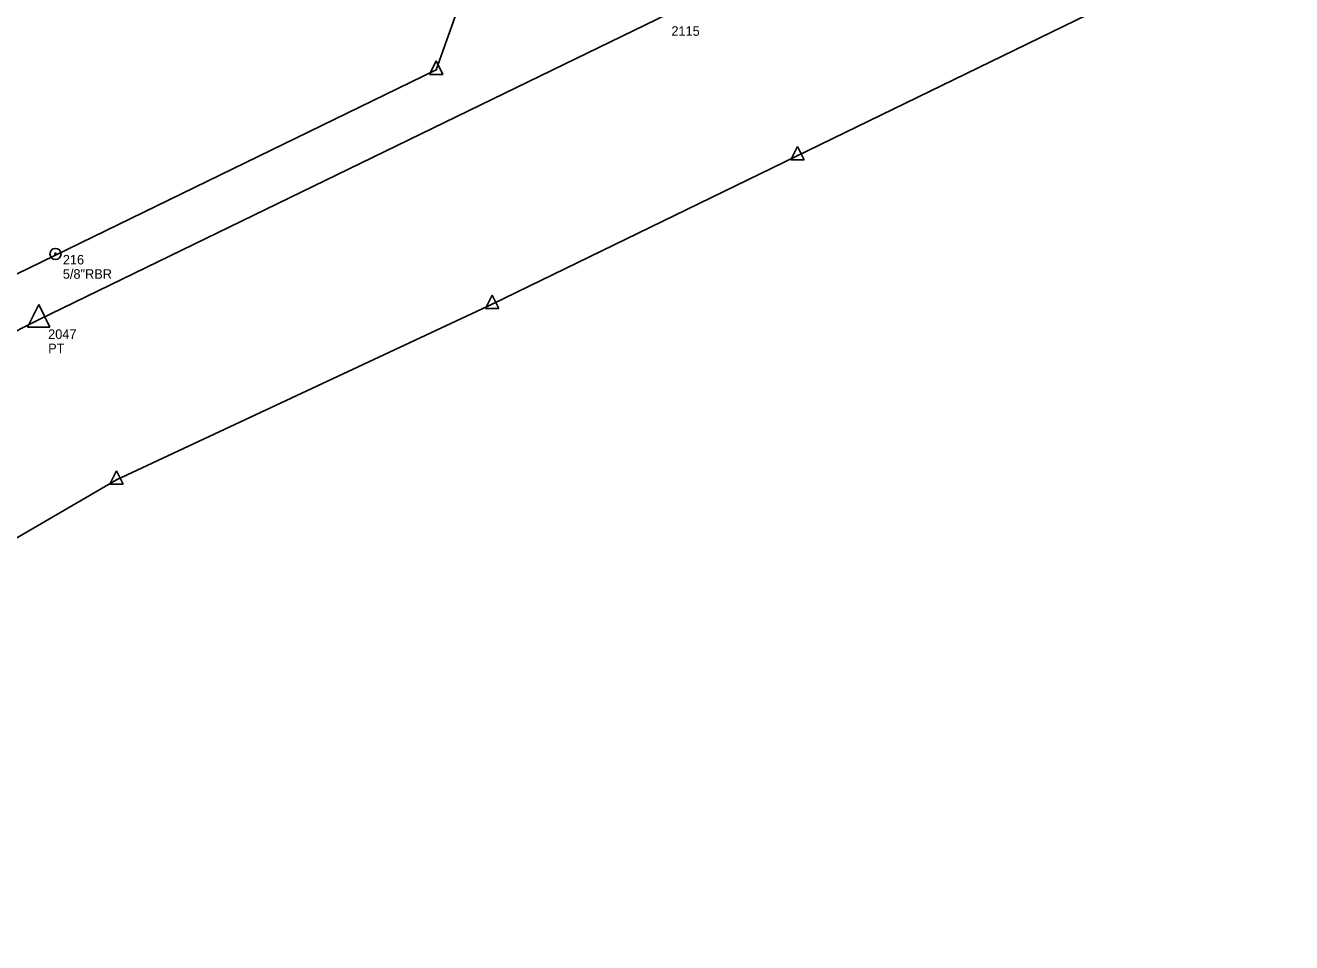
# Model space of a CAD drawing. Extents: x 1674300 to 1677920, y 225056 to 231852.
# Drawn here: x 1675417 to 1676414, y 226643 to 227365 of the extents above; entities that cross this region are included whole.
import ezdxf

# ---------------------------------------------------------------- set-up
doc = ezdxf.new("R2010")
doc.units = 0
for name, color, linetype in [('S_CAL_CORNER', 7, 'Continuous'), ('S_CAL_CORNER_ANNOT', 7, 'Continuous'), ('S_EXIST_ROW', 7, 'Continuous'), ('S_EXISTING_ALIGNMENT', 7, 'Continuous'), ('S_IRON_PIN', 7, 'Continuous'), ('S_IRON_PIN_ANNOT', 7, 'Continuous')]:
    doc.layers.add(name, color=color, linetype=linetype)

msp = doc.modelspace()

# ---------------------------------------------------------------- linework, layer by layer
at = {"layer": 'S_CAL_CORNER'}
for p, q in [((1675427.62, 227145.4), (1675418.8, 227127.67)), ((1675427.62, 227145.4), (1675418.8, 227127.67)), ((1675427.62, 227145.4), (1675436.34, 227127.67)), ((1675427.62, 227145.4), (1675436.34, 227127.67)), ((1675418.8, 227127.67), (1675436.34, 227127.67)), ((1675418.8, 227127.67), (1675436.34, 227127.67))]:
    msp.add_line(p, q, dxfattribs=at)
at = {"layer": 'S_EXIST_ROW'}
for p, q in [((1675784.51, 227145.88), (1676413.97, 227452.12)), ((1675740.53, 227330.21), (1675775.31, 227429.27)), ((1675740.54, 227337.31), (1675735.26, 227326.67)), ((1675740.54, 227337.31), (1675745.78, 227326.67)), ((1675409.98, 227169.4), (1675740.53, 227330.21)), ((1675735.26, 227326.67), (1675745.78, 227326.67)), ((1675740.53, 227330.21), (1675740.53, 227330.21)), ((1676025.03, 227269.98), (1676019.74, 227259.34)), ((1676025.03, 227269.98), (1676030.26, 227259.34)), ((1676019.74, 227259.34), (1676030.26, 227259.34)), ((1676025.01, 227262.89), (1676025.01, 227262.89)), ((1675488.73, 227007.54), (1675784.51, 227145.88)), ((1675784.53, 227152.97), (1675779.24, 227142.33)), ((1675784.51, 227145.88), (1675784.51, 227145.88)), ((1675784.53, 227152.97), (1675789.76, 227142.33)), ((1675779.24, 227142.33), (1675789.76, 227142.33)), ((1675357, 226930.8), (1675488.73, 227007.54)), ((1675488.75, 227014.63), (1675483.46, 227003.99)), ((1675488.73, 227007.54), (1675488.73, 227007.54)), ((1675488.75, 227014.63), (1675493.98, 227003.99)), ((1675483.46, 227003.99), (1675493.98, 227003.99))]:
    msp.add_line(p, q, dxfattribs=at)
for centre, radius in [((1675740.53, 227330.21), 0.18), ((1675740.53, 227330.21), 0.09), ((1676025.01, 227262.89), 0.18), ((1676025.01, 227262.89), 0.09), ((1675784.51, 227145.88), 0.18), ((1675784.51, 227145.88), 0.09), ((1675488.73, 227007.54), 0.18), ((1675488.73, 227007.54), 0.09)]:
    msp.add_circle(centre, radius, dxfattribs=at)
at = {"layer": 'S_EXISTING_ALIGNMENT'}
for p, q in [((1675841.07, 227334.65), (1676112.44, 227466.67)), ((1675427.48, 227133.43), (1675841.07, 227334.65))]:
    msp.add_line(p, q, dxfattribs=at)
msp.add_arc((1675935.58, 226089.07), 1161.4, 115.94359, 151.51603, dxfattribs=at)
at = {"layer": 'S_IRON_PIN'}
for radius in [4.36, 0.617, 0.392, 0.317, 0.218, 0.123, 0.0872]:
    msp.add_circle((1675440.76, 227185.37), radius, dxfattribs=at)

# ---------------------------------------------------------------- texts
at = {"layer": 'S_CAL_CORNER_ANNOT'}
for s, p in [('2115', (1675925.63, 227357.14)), ('2047', (1675434.98, 227118.43)), ('2047', (1675434.98, 227118.43)), ('PT', (1675434.98, 227107.18)), ('PT', (1675434.98, 227107.18))]:
    msp.add_text(s, height=7.5, dxfattribs=at).set_placement(p)
at = {"layer": 'S_IRON_PIN_ANNOT'}
for s, p in [('216', (1675446.55, 227177.06)), ('5/8"RBR ', (1675446.55, 227165.81))]:
    msp.add_text(s, height=7.5, dxfattribs=at).set_placement(p)

doc.saveas('drawing.dxf')
